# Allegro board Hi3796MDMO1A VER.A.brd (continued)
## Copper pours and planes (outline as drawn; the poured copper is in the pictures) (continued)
$4N773 on TOP: 91.57,59.99 95.63,59.99 95.76,59.87 95.76,58.47 95.12,57.84 93.98,57.84 93.47,57.33 93.47,56.31 93.34,56.18 91.69,56.18 91.44,56.44 91.44,59.87
$4N810 on TOP (solid shape): 72.24,29.15 72.24,27.39 72.15,27.3 69.15,27.3 68.56,26.72 68.56,24.94 68.53,24.91 67.86,24.91 67.36,25.41 67.36,27.27 68.11,28.02 68.11,29.17 68.23,29.28 72.1,29.28
$4N878 on TOP: 37.26,73.15 37.21,73.2 37.21,74.68 37.72,75.18 42.04,75.18 42.16,75.06 42.16,71.5 42.04,71.37 40.26,71.37 40.13,71.5 40.13,72.9 39.88,73.15
$4N1055 on TOP: 27.3,74.85 27.3,81.28 27.43,81.41 29.34,81.41 29.34,76.5 29.21,76.38 28.19,76.38 28.07,76.25 28.07,74.85 27.94,74.73 27.43,74.73
$4N1115 on TOP (solid shape): 62.96,21.78 62.96,20.02 62.88,19.94 60.07,19.94 59.29,19.16 59.29,17.6 59.29,17.6 58.64,17.6 58.64,17.6 58.37,17.6 58.14,17.83 58.14,19.56 58.14,19.56 58.14,19.76 58.46,20.08 58.46,21.55 58.82,21.91 62.83,21.91
$14N657 on TOP: 18.41,55.12 19.43,56.13 21.72,56.13 21.84,56.01 21.84,52.2 21.62,51.98 21.62,50.69 21.48,50.55 20.19,50.55 20.07,50.67 20.07,52.45 19.32,53.2 11.19,53.2 11.05,53.35 11.05,54.99 11.18,55.12
$14N657 on POWER03: 13.21,54.99 13.27,54.93 13.27,51.29 10.67,48.69 10.67,47.24 10.29,46.86 9.14,46.86 8.64,47.37 8.64,48.64 9.4,49.4 9.4,49.91 10.79,51.31 10.79,54.74 11.05,54.99
$17N163 on TOP (solid shape): 36.25,88.25 37.11,88.25 37.23,88.13 37.23,87.87 36.88,87.53 36.88,85.67 36.87,85.66 36.27,85.66 36.25,85.68 36.25,87.58 35.97,87.86 35.97,88.12 36.09,88.25 36.25,88.25
$17N163 on BOTTOM (solid shape): 37.54,88.12 37.54,86.91 35.92,86.91 35.92,87.12 37.08,87.12 37.08,87.38 36.83,87.38 36.83,87.12 36.58,87.12 36.58,87.38 36.32,87.38 36.32,87.12 35.92,87.12 35.92,88.16 36.01,88.26 37.4,88.26
$17N184 on TOP (solid shape): 29.9,88.2 30.76,88.2 30.88,88.08 30.88,87.82 30.53,87.48 30.53,85.62 30.52,85.61 29.92,85.61 29.9,85.63 29.9,87.53 29.62,87.81 29.62,88.07 29.74,88.2 29.9,88.2
$17N184 on BOTTOM (solid shape): 30.98,88.12 30.98,86.87 30.98,86.86 29.37,86.86 29.37,86.87 29.37,87.25 30.61,87.25 30.61,87.5 30.23,87.5 30.23,87.25 30.1,87.25 30.1,87.5 29.72,87.5 29.72,87.25 29.37,87.25 29.37,87.66 29.5,87.79 29.5,88.19 29.56,88.26 30.85,88.26
$20N444 on TOP: 94.49,76.33 93.09,76.33 92.96,76.2 92.96,74.04 93.09,73.91 94.36,73.91 94.61,74.17 94.61,76.2
$20N444 on TOP: 84.66,80.39 85.47,80.39 85.6,80.26 85.6,79.02 83.95,77.37 83.95,76.26 83.76,76.08 77.08,76.08 76.83,76.33 76.83,78.23 76.71,78.36 73.15,78.36 73.09,78.42 73.09,79.57 73.15,79.63 76.71,79.63 76.83,79.76 76.83,81.67 77.02,81.86 84.06,81.86 84.3,81.61 84.3,81.61 84.3,80.75 ; 1 cut-out
$20N444 on BOTTOM: 84.27,79.76 85.22,79.76 86.36,78.61 86.36,78.61 86.53,78.45 90.3,78.45 90.91,77.83 94.46,77.83 94.82,77.47 94.82,75.65 94.71,75.55 93.34,75.55 93.21,75.68 93.21,76.75 92.99,76.97 84.52,76.97 84.34,76.8 84.34,76.02 84.52,75.84 85.32,75.84 85.4,75.76 85.4,74.85 85.36,74.81 83.15,74.81 82.99,74.97 82.15,74.97 81.95,75.16 81.95,77.44
$21N629 on TOP: 128.91,94.83 128.91,96.38 129.12,96.58 132.14,96.58 132.24,96.48 132.24,94.21 131.88,93.84 129.9,93.84
$21N629 on BOTTOM: 127.76,96.4 127.76,93.47 127.96,93.26 130.48,93.26 130.67,93.45 130.67,96.18 130.35,96.5 127.89,96.5 127.79,96.4 ; 1 cut-out
$21N844 on TOP: 108.46,64.9 108.46,68.67 109.69,69.9 114.12,69.9 114.5,69.53 114.5,67.35 114.13,67.35 114.13,69.12 114.02,69.23 113.23,69.23 111.72,67.72 111.72,63.73 110.45,62.46 104.52,62.46 104.01,62.97 104.01,64.29 104.24,64.52 108.08,64.52
$21N851 on TOP: 115.98,76.48 116.04,76.42 116.04,70.4 115.78,70.14 115.78,67.36 115.77,67.35 115.44,67.35 115.43,67.36 115.43,69.86 114.94,70.36 114.94,70.87 114.76,71.04 113.63,71.04 113.28,71.4 113.28,72.67 112.52,73.43 112.06,73.43 111.99,73.36 109.09,73.36 108.71,73.74 108.71,75.16 108.84,75.29 111.43,75.29 111.46,75.31 111.46,78.08 111.71,78.33 114.94,78.33 115.98,77.29 ; 1 cut-out
$21N859 on TOP: 107.2,68.57 107.2,65.65 107.01,65.46 103.68,65.46 103.38,65.76 103.38,72.64 103.76,73.02 106.15,73.02 106.98,72.19 112.52,72.19 112.62,72.09 112.62,70.36 112.52,70.26 108.89,70.26
$21N880 on TOP: 115.95,69.34 115.95,70.1 116.47,70.62 116.47,72.91 117.47,73.91 117.47,76.58 118.11,77.22 123.19,77.22 123.34,77.06 123.34,74.8 123.57,74.57 123.57,70.31 124.59,69.29 124.59,65.58 124.31,65.3 121.36,65.3 120.9,65.76 120.9,72.39 120.14,73.15 119.13,73.15 118.36,72.39 117.86,72.39 117.6,72.14 117.6,70.48 116.43,69.31 116.43,67.4 116.43,67.4 116.43,67.37 116.4,67.35 116.11,67.35 116.08,67.38 116.08,69.21

Small or netless copper shapes (teardrops, artwork), in the pictures only: 4 on TOP

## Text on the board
BOTTOM: HI3796MDMO1A VER.A ARTWORK BOTTOM
Ref Des/Silkscreen Bottom: HI3796MDMO1A VER.A SILKSCREEN BOTTOM
User.Comments: 1 | 2 | 7 | 8 | 19 | 3 | 4 | 23 | 24 | PCB EDGE | CARD DASHING POSITION | CARD LOCK POSITION | CARD PUSH POSITION | 9 | 5 | 6 | HI3796MDMO1A VER.A SOLDMASK TOP | HI3796MDMO1A VER.A SOLDMASK BOTTOM
TOP: HI3796MDMO1A VER.A ARTWORK TOP
Ref Des/Silkscreen Top: HI3796MDMO1A VER.A | HI3796MDMO1A VER.A SILKSCREEN TOP
GND02: HI3796MDMO1A VER.A ARTWORK LAYER02
POWER03: HI3796MDMO1A VER.A ARTWORK LAYER03
DIMENSION: Single Impedance | Diff Impedance | 100 ohm | 90 ohm | 75 ohm | 50 ohm | PREPREG | GND02 | ART01 | ART04 | POWWE03 | CORE | Layer | 1,4 | 1 | Trace Width(mil) | Trace W/S(mil) | 4.5/6.0 | 6.0/7.0 | Layer Stack up | Solder Bot | Silk Bot | 5 | 20.01 | Solder Top | 15.01 | Silk Top | Tolerance | + | - | 10% | Frequency(MHZ) | Default | Thickness (mil) | 1.8(0.5oz+plating) | 4.0 | 1.2(1.0oz) | XXX | Ref04 | Remark | Notes3: | For this PN,Soldermask should be covered at all required location and | no red solder(copper color) is allowed at BGA area | 4X | 2X | 2XOBLONG VIA 36X105MIL | 2XOBLONG VIA 36X82MIL | 5XOBLONG VIA 52X24MIL | OBLONG VIA 120X40MIL | OBLONG VIA 40X120MIL | OBLONG VIA 40X135MIL | OBLONG VIA 100X40MIL | OBLONG VIA 50X180MIL | OBLONG VIA 40X70MIL | HI3796MDMO1A VER.A DRILL CHART
DISPLAY_BOTTOM: HI3796MDMO1A VER.A PASTEMASK BOTTOM
DISPLAY_TOP: HI3796MDMO1A VER.A PASTEMASK TOP
User.11: FIGURE | SIZE | 8.0 | 10.0 | 12.0 | 20.0 | 30.0 | 32.0 | 36.0 | 38.0 | 40.0 | 52.0 | 90.0 | 95.0 | 43.0 | 80.0 | 135.0 | 138.0 | 52.0x24.0 | 70.0x40.0 | 82.0x36.0 | 100.0x40.0 | 105.0x36.0 | 120.0x40.0 | 135.0x40.0 | 180.0x50.0 | DRILL CHART: TOP to BOTTOM | ALL UNITS ARE IN MILS | TOLERANCE | +0.0/-0.0 | +3.0/-3.0 | +2.0/-2.0 | PLATED | NON-PLATED | QTY | 584 | 1859 | 32 | 4 | 9 | 3 | 12 | 15 | 33 | 8 | 2 | 42 | 5 | 1
